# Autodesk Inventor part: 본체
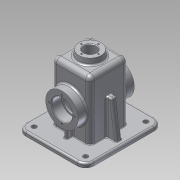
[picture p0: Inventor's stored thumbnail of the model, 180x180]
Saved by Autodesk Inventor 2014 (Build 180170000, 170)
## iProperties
Created: 2016-08
Part Number: 본체
Material: 알루미늄 6061
Document SubType Name: Modeling
Designer: user
Density: 2.71 g/cm^3
Appearance: 알루미늄 - 평지
Mass: 795.975 g
Surface Area: 911.439 cm^2
Volume: 293.718 cm^3
Author: user
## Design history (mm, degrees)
sketch "스케치2"
  geometry: L1 (-57.5, -65)-(57.5, -65); L2 (57.5, -65)-(57.5, 65); L3 (57.5, 65)-(-57.5, 65); L4 (-57.5, 65)-(-57.5, -65); 3 further points
  constraints: 8 end point, 2 midpoint, 2 parallel, 1 horizontal, 1 horizontal alignment, 1 perpendicular, 1 vertical alignment
  dimensions: "d0" = 130 distance of L1.end L2.end; "d1" = 115 distance of L2.end L3.end
extrude "돌출1" new body sketch "스케치2" distance "d2" = 10; taper "d3" = 0 deg
sketch "스케치3"
  geometry: L1 (57.5, -65)-(-57.5, -65) reference; L2 (57.5, 65)-(57.5, -65) reference; L3 (-57.5, 65)-(57.5, 65) reference; L4 (-57.5, -65)-(-57.5, 65) reference; L5 (-52.5, 60)-(52.5, 60); L6 (52.5, 60)-(52.5, -60); L7 (52.5, -60)-(-52.5, -60); L8 (-52.5, -60)-(-52.5, 60); 1 further point
  constraints: 8 end point, 3 other
  dimensions: "d8" = 5 distance between parallel lines of L8 L4
extrude "돌출2" cut sketch "스케치3" distance "d6" = 3; taper "d7" = 0 deg
sketch "스케치4"
  geometry: L1 (-32.5, 32.5)-(32.5, 32.5); L2 (32.5, 32.5)-(32.5, -32.5); L3 (32.5, -32.5)-(-32.5, -32.5); L4 (-32.5, -32.5)-(-32.5, 32.5); 3 further points
  constraints: 8 end point, 2 midpoint, 2 parallel, 2 perpendicular, 1 horizontal, 1 horizontal alignment, 1 vertical alignment
  dimensions: "d11" = 65 distance of L1.start L1.end
extrude "돌출3" join sketch "스케치4" distance "d13" = 100; taper "d14" = 0 deg
sketch "스케치5"
  geometry: C1 r 20 at (0, 0); 1 further point
  constraints: 1 centre point, 1 coincident
  dimensions: "d15" = 40 diameter of C1
extrude "돌출4" join sketch "스케치5" distance "d16" = 10; taper "d17" = 0 deg
feature "면 기울기1" dims angle "d18" = 7 deg
sketch "스케치6"
  geometry: L1 (52.5, 3)-(52.5, 0) reference; L2 (52.5, 0)-(-52.5, 0) reference; L3 (-52.5, 0)-(-52.5, 3) reference; L4 (-52.5, 3)-(-57.5, 3) reference; L5 (-57.5, 3)-(-57.5, 10) reference; L6 (-57.5, 10)-(-32.5, 10) reference; L7 (-32.5, 10)-(-32.5, 110) reference; L8 (-32.5, 110)-(-20, 110) reference; L9 (-20, 110)-(-18.772, 120) reference; L10 (-18.772, 120)-(18.772, 120) reference; L11 (18.772, 120)-(20, 110) reference; L12 (20, 110)-(32.5, 110) reference; L13 (32.5, 110)-(32.5, 10) reference; L14 (32.5, 10)-(57.5, 10) reference; L15 (57.5, 10)-(57.5, 3) reference; L16 (57.5, 3)-(52.5, 3) reference; L17 (-49.5, 10)-(-41.068, 70); L18 (-41.068, 70)-(-32.5, 70); 1 further point
  constraints: 4 end point, 2 point on line, 1 perpendicular
  dimensions: "d19" = 8 horizontal distance of L4.end L17.start; "d20" = 8 deg angle of L5 L17; "d21" = 70 vertical distance of L2.end L17.end
feature "리브1" sketch "스케치6" dims "d22" = 1, "d23" = 10, "d24" = 0, "d25" = 0, "d26" = 1, "d27" = 1
sketch "스케치8"
  geometry: C1 r 27.5 at (0, 55); 1 further point
  constraints: 1 centre point
  dimensions: "d31" = 55 diameter of C1; "d32" = 55 distance of point (0, 0) C1.centre
extrude "돌출5" join sketch "스케치8" stored distance "d33" = 95; taper "d34" = 0 deg
sketch "스케치9"
  geometry: L1 (18.772, 120)-(20, 110) reference; L2 (20, 110)-(32.5, 110) reference; L3 (32.5, 110)-(32.5, 82.5) reference; L4 (32.5, 82.5)-(47.5, 82.5) reference; L5 (47.5, 82.5)-(47.5, 27.5) reference; L6 (47.5, 27.5)-(32.5, 27.5) reference; L7 (32.5, 27.5)-(32.5, 10) reference; L8 (32.5, 10)-(65, 10) reference; L9 (65, 10)-(65, 3) reference; L10 (65, 3)-(60, 3) reference; L11 (60, 3)-(60, 0) reference; L12 (60, 0)-(-60, 0) reference; L13 (-60, 0)-(-60, 3) reference; L14 (-60, 3)-(-65, 3) reference; L15 (-65, 3)-(-65, 10) reference; L16 (-65, 10)-(-32.5, 10) reference; L17 (-32.5, 10)-(-32.5, 27.5) reference; L18 (-32.5, 27.5)-(-47.5, 27.5) reference; L19 (-47.5, 27.5)-(-47.5, 82.5) reference; L20 (-47.5, 82.5)-(-32.5, 82.5) reference; L21 (-32.5, 82.5)-(-32.5, 110) reference; L22 (-32.5, 110)-(-20, 110) reference; L23 (-20, 110)-(-18.772, 120) reference; L24 (-18.772, 120)-(18.772, 120) reference; L25 (-27.5, 105)-(27.5, 105); L26 (27.5, 105)-(27.5, 0); L27 (27.5, 0)-(-27.5, 0); L28 (-27.5, 0)-(-27.5, 105); 1 further point
  constraints: 8 end point, 2 parallel, 1 horizontal, 1 perpendicular, 1 point on line
  dimensions: "d35" = 5 distance between parallel lines of L28 L21; "d36" = 5 distance between parallel lines of L3 L26; "d37" = 5 distance between parallel lines of L25 L22
extrude "돌출6" cut sketch "스케치9" stored distance "d38" = 55; taper "d39" = 0 deg
sketch "스케치10"
  geometry: L1 (18.772, 120)-(20, 110) reference; L2 (20, 110)-(32.5, 110) reference; L3 (32.5, 110)-(32.5, 82.5) reference; L4 (32.5, 82.5)-(47.5, 82.5) reference; L5 (47.5, 82.5)-(47.5, 27.5) reference; L6 (47.5, 27.5)-(32.5, 27.5) reference; L7 (32.5, 27.5)-(32.5, 10) reference; L8 (32.5, 10)-(65, 10) reference; L9 (65, 10)-(65, 3) reference; L10 (65, 3)-(60, 3) reference; L11 (60, 3)-(60, 0) reference; L12 (60, 0)-(27.5, 0) reference; L13 (27.5, 0)-(27.5, 105) reference; L14 (27.5, 105)-(-27.5, 105) reference; L15 (-27.5, 105)-(-27.5, 0) reference; L16 (-27.5, 0)-(-60, 0) reference; L17 (-60, 0)-(-60, 3) reference; L18 (-60, 3)-(-65, 3) reference; L19 (-65, 3)-(-65, 10) reference; L20 (-65, 10)-(-32.5, 10) reference; L21 (-32.5, 10)-(-32.5, 27.5) reference; L22 (-32.5, 27.5)-(-47.5, 27.5) reference; L23 (-47.5, 27.5)-(-47.5, 82.5) reference; L24 (-47.5, 82.5)-(-32.5, 82.5) reference; L25 (-32.5, 82.5)-(-32.5, 110) reference; L26 (-32.5, 110)-(-20, 110) reference; L27 (-20, 110)-(-18.772, 120) reference; L28 (-18.772, 120)-(18.772, 120) reference; L29 (-42.5, 10)-(-42.5, 30); 1 further point
  constraints: 2 end point, 1 perpendicular, 1 point on line
  dimensions: "d40" = 15 distance from line of L29.start L15; "d41" = 20 distance of L29.start L29.end
feature "리브2" sketch "스케치10" dims "d42" = 1, "d43" = 6, "d44" = 0, "d45" = 0, "d46" = 1, "d47" = 1
sketch "스케치11"
  geometry: C1 r 27.5 at (0, 0) reference; 1 further point
hole "구멍1" sketch "스케치11" at (0, 0) diameter "d48" = 30; stored, may be unused: countersink angle "d52" = 90 deg, drill point angle "d54" = 0 deg; dims "d49" = 6, "d50" = 35, "d51" = 17, "d53" = 8
sketch "스케치12"
  geometry: C1 r 18.772 at (0, 0) reference
hole "구멍2" sketch "스케치12" at (0, 0) diameter "d55" = 21; stored, may be unused: countersink angle "d59" = 90 deg, drill point angle "d61" = 0 deg; dims "d56" = 6, "d57" = 35, "d58" = 17, "d60" = 8
sketch "스케치13" dims "d62" = 42
  geometry: C1 r 17.5 at (0, 0) reference; C2 r 27.5 at (0, 0) reference; 6 further points
  constraints: 2 vertical alignment, 1 coincident, 7 other
  dimensions: "d65" = 360 deg dimension on C1.centre point (0, 21) (derived)
hole "구멍3" sketch "스케치13" at (0, 21), (-21, 0), (0, -21), (21, 0), (0, 0) diameter "d67" = 3.242; stored, may be unused: countersink angle "d71" = 90 deg, drill point angle "d73" = 118 deg; dims "d68" = 8, "d69" = 35, "d70" = 17, "d72" = 10
sketch "스케치14" dims "d74" = 29
  geometry: C1 r 10.5 at (0, 0) reference; C2 r 18.772 at (0, 0) reference; 5 further points
  constraints: 2 vertical alignment, 1 coincident, 7 other
  dimensions: "d77" = 360 deg dimension on C1.centre point (0, 14.5) (derived)
hole "구멍4" sketch "스케치14" at (0, 14.5), (-14.5, 0), (0, -14.5), (14.5, 0) diameter "d79" = 2.459; stored, may be unused: countersink angle "d83" = 90 deg, drill point angle "d85" = 118 deg; dims "d80" = 7, "d81" = 35, "d82" = 17, "d84" = 9
fillet "모깎기4" dims "d86" = 8
fillet "모깎기5" dims "d87" = 8
fillet "모깎기6" dims "d88" = 14
fillet "모깎기7" dims "d89" = 9
sketch "스케치15"
  geometry: A1 r 14 centre (-43.5, -51) between (-57.5, -51) and (-43.5, -65) reference; A2 r 14 centre (43.5, -51) between (43.5, -65) and (57.5, -51) reference; A3 r 14 centre (43.5, 51) between (57.5, 51) and (43.5, 65) reference; A4 r 14 centre (-43.5, 51) between (-43.5, 65) and (-57.5, 51) reference; 1 further point
hole "구멍5" sketch "스케치15" at (43.5, 51), (-43.5, 51), (-43.5, -51), (43.5, -51) diameter "d90" = 8; stored, may be unused: countersink angle "d94" = 90 deg, drill point angle "d96" = 0 deg; dims "d91" = 7, "d92" = 35, "d93" = 17, "d95" = 9
fillet "모깎기8" dims "d97" = 3
fillet "모깎기9" dims "d98" = 3
fillet "모깎기10" dims "d99" = 3
fillet "모깎기11" dims "d100" = 3
fillet "모깎기12" dims "d101" = 3
fillet "모깎기13" dims "d102" = 3
chamfer "모따기1" distance "d103" = 1; stored, may be unused: second distance "d104" = 2, angle "d105" = 45 deg
chamfer "모따기2" distance "d106" = 1; stored, may be unused: second distance "d107" = 2, angle "d108" = 45 deg
fillet "모깎기14" dims "d109" = 1
fillet "모깎기15" dims "d110" = 3
fillet "모깎기16" dims "d111" = 3
fillet "모깎기17" dims "d112" = 3
node "작업 평면1"
sketch "스케치16"
  geometry: L1 (5.728, -18)-(43.272, -18) reference; L2 (57, 0)-(57, 91) reference; 2 further points
  constraints: 1 other
  dimensions: "d115" = 32.5 distance from line of point (24.5, 8) L2; "d116" = 26 distance from line of point (24.5, 8) L1
feature "엠보싱1" sketch "스케치16" dims "d8" = 5, "d117" = 0.5, "d118" = 0
fillet "모깎기18" dims "d119" = 0.3
node "솔리드1"
mirror "대칭1"
mirror "대칭2"
mirror "대칭3"
mirror "대칭4"
node "절단 모서리 투영1"
node "절단 모서리 투영2"
node "절단 모서리 투영3"
